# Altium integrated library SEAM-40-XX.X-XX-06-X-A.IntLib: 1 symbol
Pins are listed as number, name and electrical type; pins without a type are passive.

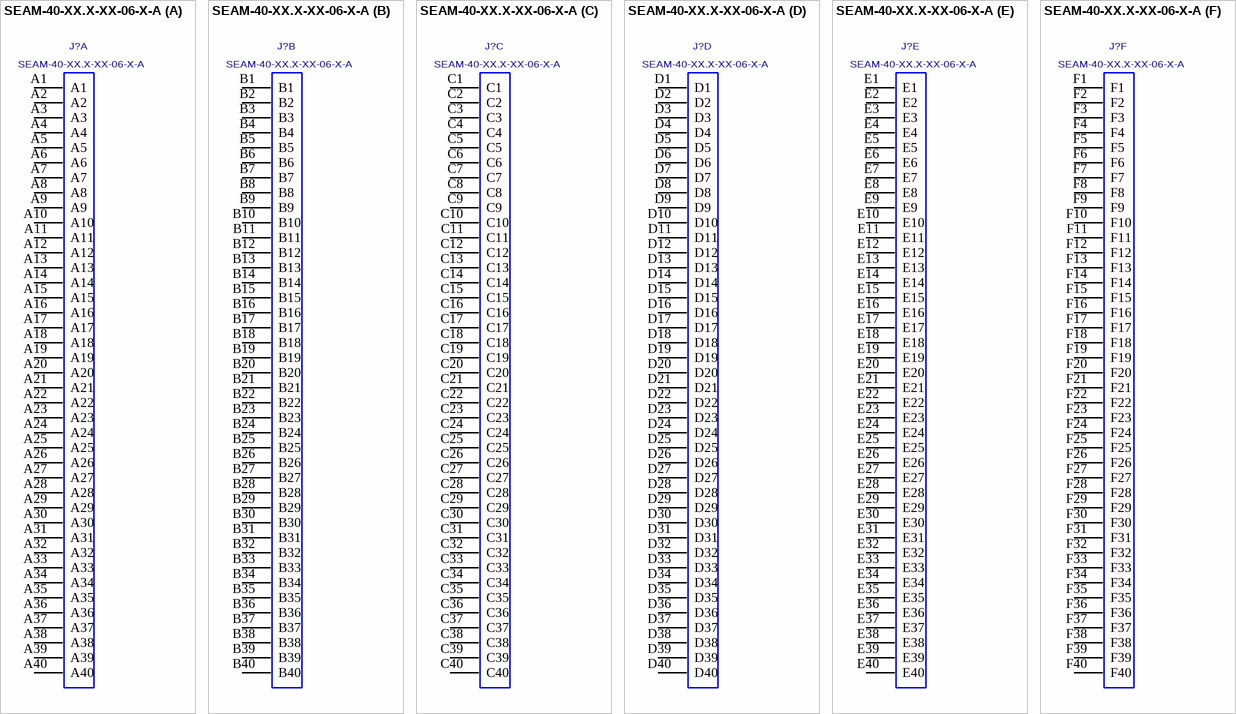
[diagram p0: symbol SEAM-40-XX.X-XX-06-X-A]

## SEAM-40-XX.X-XX-06-X-A
designator J?
Terminal  Array Assembly, Surface Mount, 0.050" Pitch, 240 Pins.; MANUFACTURER: SAMTEC
footprint SEAM-40-XX.X-XX-06-X-A
part A pins: A1, A2, A3, A4, A5, A6, A7, A8, A9, A10, A11, A12, A13, A14, A15, A16, A17, A18, A19, A20, A21, A22, A23, A24, A25, A26, A27, A28, A29, A30, A31, A32, A33, A34, A35, A36, A37, A38, A39, A40
part B pins: B1, B2, B3, B4, B5, B6, B7, B8, B9, B10, B11, B12, B13, B14, B15, B16, B17, B18, B19, B20, B21, B22, B23, B24, B25, B26, B27, B28, B29, B30, B31, B32, B33, B34, B35, B36, B37, B38, B39, B40
part C pins: C1, C2, C3, C4, C5, C6, C7, C8, C9, C10, C11, C12, C13, C14, C15, C16, C17, C18, C19, C20, C21, C22, C23, C24, C25, C26, C27, C28, C29, C30, C31, C32, C33, C34, C35, C36, C37, C38, C39, C40
part D pins: D1, D2, D3, D4, D5, D6, D7, D8, D9, D10, D11, D12, D13, D14, D15, D16, D17, D18, D19, D20, D21, D22, D23, D24, D25, D26, D27, D28, D29, D30, D31, D32, D33, D34, D35, D36, D37, D38, D39, D40
part E pins: E1, E2, E3, E4, E5, E6, E7, E8, E9, E10, E11, E12, E13, E14, E15, E16, E17, E18, E19, E20, E21, E22, E23, E24, E25, E26, E27, E28, E29, E30, E31, E32, E33, E34, E35, E36, E37, E38, E39, E40
part F pins: F1, F2, F3, F4, F5, F6, F7, F8, F9, F10, F11, F12, F13, F14, F15, F16, F17, F18, F19, F20, F21, F22, F23, F24, F25, F26, F27, F28, F29, F30, F31, F32, F33, F34, F35, F36, F37, F38, F39, F40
